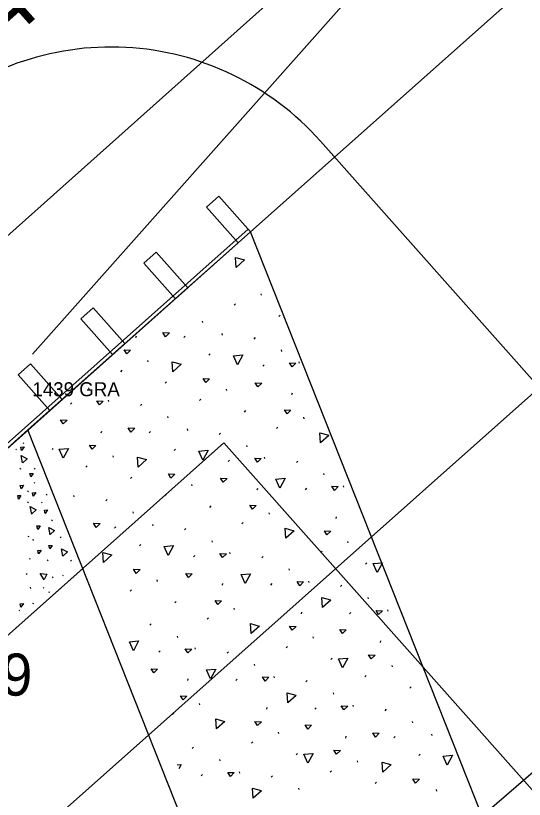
# Model space of a CAD drawing. Extents: x 49683 to 58852, y 49525 to 54803.
# Drawn here: x 55264.7 to 55301, y 53044.6 to 53100.5 of the extents above; entities that cross this region are included whole.
import ezdxf

# ---------------------------------------------------------------- set-up
doc = ezdxf.new("R2010")
doc.units = 0
for name, color, linetype in [('Level 11', 7, 'Continuous'), ('Level 13', 7, 'Continuous'), ('Level 15', 7, 'Continuous'), ('Level 18', 7, 'Continuous'), ('Level 19', 7, 'Continuous'), ('Level 20', 7, 'Continuous'), ('Level 27', 7, 'Continuous'), ('Level 3', 7, 'Continuous'), ('Level 32', 7, 'Continuous'), ('Level 48', 7, 'Continuous'), ('Level 57', 7, 'Continuous'), ('Level 7', 7, 'Continuous'), ('Level 8', 7, 'Continuous')]:
    doc.layers.add(name, color=color, linetype=linetype)

msp = doc.modelspace()

# ---------------------------------------------------------------- linework, layer by layer
at = {"layer": 'Level 11'}
msp.add_line((55223.521, 52979.087), (55416.975, 53146.156), dxfattribs=at)
at = {"layer": 'Level 13'}
for p, q in [((55279.532, 53069.998), (53969.027, 51905.114)), ((55307.435, 53038.607), (55279.532, 53069.998))]:
    msp.add_line(p, q, dxfattribs=at)
at = {"layer": 'Level 15'}
for p, q in [((55281.433, 53085.069), (55371.123, 53164.793)), ((55265.526, 53070.929), (55281.433, 53085.069)), ((55298.696, 53041.543), (55281.433, 53085.069)), ((55282.23, 53080.542), (55282.206, 53080.639)), ((55280.357, 53079.939), (55280.262, 53079.84)), ((55283.556, 53079.114), (55283.461, 53079.016)), ((55278.031, 53078.592), (55278.008, 53078.689)), ((55273.252, 53077.518), (55273.281, 53077.641)), ((55279.432, 53077.706), (55279.408, 53077.803)), ((55276.776, 53077.625), (55276.681, 53077.526)), ((55281.778, 53077.517), (55281.683, 53077.418)), ((55283.669, 53076.539), (55283.646, 53076.637)), ((55278.563, 53076.369), (55278.469, 53076.27)), ((55274.114, 53075.788), (55274.091, 53075.885)), ((55282.414, 53075.572), (55282.319, 53075.474)), ((55284.936, 53075.703), (55284.912, 53075.8)), ((55272.241, 53075.185), (55272.146, 53075.087)), ((55275.44, 53074.36), (55275.346, 53074.262)), ((55269.916, 53073.838), (55269.892, 53073.935)), ((55279.752, 53073.736), (55279.729, 53073.833)), ((55284.394, 53073.463), (55284.423, 53073.585)), ((55268.661, 53072.871), (55268.566, 53072.772)), ((55271.317, 53072.952), (55271.293, 53073.049)), ((55273.663, 53072.763), (55273.568, 53072.665)), ((55277.879, 53073.133), (55277.784, 53073.035)), ((55281.079, 53072.308), (55280.984, 53072.21)), ((55275.554, 53071.786), (55275.53, 53071.883)), ((55285.256, 53071.733), (55285.233, 53071.83)), ((55253.595, 53060.324), (55265.526, 53070.929)), ((55282.788, 53027.404), (55265.526, 53070.929)), ((55276.955, 53070.9), (55276.931, 53070.997)), ((55283.383, 53071.13), (55283.288, 53071.031)), ((55270.774, 53070.713), (55270.804, 53070.835)), ((55274.299, 53070.819), (55274.204, 53070.72)), ((55279.301, 53070.711), (55279.206, 53070.613)), ((55281.192, 53069.734), (55281.169, 53069.831)), ((55267.325, 53069.607), (55267.262, 53069.541)), ((55276.086, 53069.563), (55275.991, 53069.464)), ((55271.637, 53068.982), (55271.613, 53069.079)), ((55279.937, 53068.767), (55279.842, 53068.668)), ((55282.459, 53068.897), (55282.435, 53068.994)), ((55284.805, 53068.708), (55284.71, 53068.609)), ((55269.764, 53068.379), (55269.669, 53068.281)), ((55286.696, 53067.73), (55286.673, 53067.828)), ((55272.963, 53067.554), (55272.868, 53067.456)), ((55277.275, 53066.93), (55277.252, 53067.027)), ((55281.916, 53066.657), (55281.946, 53066.779)), ((55285.441, 53066.763), (55285.346, 53066.665)), ((55288.097, 53066.845), (55288.073, 53066.942)), ((55268.839, 53066.146), (55268.816, 53066.244)), ((55271.186, 53065.957), (55271.091, 53065.859)), ((55275.402, 53066.327), (55275.307, 53066.229)), ((55278.602, 53065.502), (55278.507, 53065.404)), ((55273.077, 53064.98), (55273.053, 53065.077)), ((55282.779, 53064.927), (55282.756, 53065.024)), ((55280.906, 53064.324), (55280.811, 53064.226)), ((55287.555, 53064.605), (55287.584, 53064.727)), ((55271.822, 53064.013), (55271.727, 53063.914)), ((55274.478, 53064.094), (55274.454, 53064.192)), ((55276.824, 53063.905), (55276.729, 53063.807)), ((55273.609, 53062.757), (55273.514, 53062.659)), ((55278.715, 53062.928), (55278.692, 53063.025)), ((55288.417, 53062.875), (55288.394, 53062.972)), ((55279.982, 53062.091), (55279.958, 53062.188)), ((55286.544, 53062.272), (55286.449, 53062.173)), ((55277.46, 53061.961), (55277.365, 53061.862)), ((55282.328, 53061.902), (55282.233, 53061.804)), ((55289.744, 53061.447), (55289.649, 53061.349)), ((55245.587, 53039.827), (55269.449, 53061.037)), ((55284.219, 53060.925), (55284.195, 53061.022)), ((55274.798, 53060.124), (55274.775, 53060.221)), ((55279.439, 53059.851), (55279.469, 53059.974)), ((55282.964, 53059.958), (55282.869, 53059.859)), ((55285.62, 53060.039), (55285.596, 53060.136)), ((55287.966, 53059.85), (55287.871, 53059.751)), ((55272.925, 53059.521), (55272.83, 53059.423)), ((55276.124, 53058.696), (55276.029, 53058.598)), ((55289.857, 53058.872), (55289.834, 53058.97)), ((55280.302, 53058.121), (55280.278, 53058.218)), ((55291.258, 53057.987), (55291.234, 53058.084)), ((55278.429, 53057.518), (55278.334, 53057.42)), ((55285.077, 53057.799), (55285.107, 53057.921)), ((55288.602, 53057.905), (55288.507, 53057.807)), ((55274.347, 53057.099), (55274.252, 53057.001)), ((55276.238, 53056.122), (55276.214, 53056.219)), ((55285.94, 53056.069), (55285.917, 53056.166)), ((55290.716, 53055.747), (55290.745, 53055.869)), ((55277.504, 53055.285), (55277.481, 53055.382)), ((55284.067, 53055.466), (55283.972, 53055.368)), ((55274.983, 53055.155), (55274.888, 53055.057)), ((55279.851, 53055.096), (55279.756, 53054.998)), ((55281.742, 53054.119), (55281.718, 53054.216)), ((55287.266, 53054.641), (55287.171, 53054.543)), ((55291.578, 53054.017), (55291.555, 53054.114)), ((55276.962, 53053.046), (55276.992, 53053.168)), ((55280.487, 53053.152), (55280.392, 53053.053)), ((55283.143, 53053.233), (55283.119, 53053.33)), ((55285.489, 53053.044), (55285.394, 53052.946)), ((55289.705, 53053.414), (55289.61, 53053.315)), ((55292.905, 53052.589), (55292.81, 53052.491)), ((55287.38, 53052.067), (55287.356, 53052.164)), ((55277.825, 53051.315), (55277.801, 53051.412)), ((55282.6, 53050.993), (55282.63, 53051.116)), ((55286.125, 53051.1), (55286.03, 53051.001)), ((55288.781, 53051.181), (55288.757, 53051.278)), ((55291.127, 53050.992), (55291.032, 53050.893)), ((55275.952, 53050.712), (55275.857, 53050.614)), ((55293.018, 53050.014), (55292.995, 53050.112)), ((55283.463, 53049.263), (55283.439, 53049.36)), ((55294.419, 53049.129), (55294.395, 53049.226)), ((55281.59, 53048.66), (55281.495, 53048.562)), ((55288.239, 53048.941), (55288.268, 53049.063)), ((55291.763, 53049.047), (55291.668, 53048.949)), ((55277.374, 53048.29), (55277.279, 53048.192)), ((55284.789, 53047.835), (55284.694, 53047.737)), ((55293.55, 53047.792), (55293.456, 53047.693)), ((55279.265, 53047.313), (55279.241, 53047.41)), ((55289.101, 53047.211), (55289.078, 53047.308)), ((55278.01, 53046.346), (55277.915, 53046.247)), ((55280.665, 53046.427), (55280.642, 53046.524)), ((55287.228, 53046.608), (55287.133, 53046.51)), ((55283.012, 53046.238), (55282.917, 53046.14)), ((55290.427, 53045.783), (55290.333, 53045.685)), ((55284.903, 53045.261), (55284.879, 53045.358)), ((55294.739, 53045.159), (55294.716, 53045.256))]:
    msp.add_line(p, q, dxfattribs=at)
for points in [[(55281.007, 53083.062), (55280.413, 53082.525), (55280.363, 53083.237), (55280.994, 53083.066)], [(55275.644, 53077.856), (55275.369, 53077.587), (55275.179, 53077.877), (55275.644, 53077.856)], [(55272.869, 53076.625), (55272.594, 53076.356), (55272.404, 53076.647), (55272.869, 53076.625)], [(55280.877, 53076.285), (55280.503, 53075.577), (55280.211, 53076.229), (55280.863, 53076.285)], [(55276.485, 53075.617), (55275.891, 53075.081), (55275.84, 53075.793), (55276.472, 53075.622)], [(55284.674, 53075.695), (55284.399, 53075.426), (55284.209, 53075.717), (55284.674, 53075.695)], [(55278.507, 53074.573), (55278.232, 53074.304), (55278.042, 53074.595), (55278.507, 53074.573)], [(55282.234, 53074.272), (55281.959, 53074.003), (55281.769, 53074.294), (55282.234, 53074.272)], [(55270.92, 53072.994), (55270.645, 53072.725), (55270.456, 53073.015), (55270.92, 53072.994)], [(55284.322, 53072.344), (55284.047, 53072.075), (55283.858, 53072.365), (55284.322, 53072.344)], [(55268.331, 53071.625), (55268.056, 53071.356), (55267.867, 53071.646), (55268.331, 53071.625)], [(55273.167, 53071.05), (55272.892, 53070.781), (55272.702, 53071.071), (55273.167, 53071.05)], [(55287.03, 53070.541), (55286.436, 53070.004), (55286.385, 53070.716), (55287.017, 53070.545)], [(55270.392, 53069.819), (55270.117, 53069.55), (55269.927, 53069.841), (55270.392, 53069.819)], [(55268.436, 53069.615), (55268.061, 53068.907), (55267.77, 53069.56), (55268.422, 53069.615)], [(55278.4, 53069.479), (55278.025, 53068.771), (55277.734, 53069.423), (55278.386, 53069.479)], [(55274.008, 53068.811), (55273.414, 53068.275), (55273.363, 53068.987), (55273.995, 53068.816)], [(55282.197, 53068.889), (55281.922, 53068.62), (55281.732, 53068.911), (55282.197, 53068.889)], [(55276.03, 53067.767), (55275.755, 53067.498), (55275.565, 53067.789), (55276.03, 53067.767)], [(55279.756, 53067.466), (55279.481, 53067.197), (55279.292, 53067.488), (55279.756, 53067.466)], [(55283.904, 53067.476), (55283.529, 53066.768), (55283.238, 53067.42), (55283.89, 53067.476)], [(55287.701, 53066.886), (55287.426, 53066.617), (55287.236, 53066.907), (55287.701, 53066.886)], [(55281.845, 53065.538), (55281.57, 53065.269), (55281.38, 53065.559), (55281.845, 53065.538)], [(55270.69, 53064.244), (55270.415, 53063.975), (55270.225, 53064.266), (55270.69, 53064.244)], [(55284.553, 53063.735), (55283.959, 53063.198), (55283.908, 53063.91), (55284.54, 53063.739)], [(55287.172, 53063.712), (55286.897, 53063.443), (55286.707, 53063.733), (55287.172, 53063.712)], [(55275.923, 53062.673), (55275.548, 53061.965), (55275.257, 53062.618), (55275.909, 53062.673)], [(55271.531, 53062.006), (55270.937, 53061.469), (55270.886, 53062.181), (55271.518, 53062.01)], [(55279.72, 53062.083), (55279.445, 53061.814), (55279.255, 53062.105), (55279.72, 53062.083)], [(55290.854, 53061.455), (55290.479, 53060.748), (55290.188, 53061.4), (55290.84, 53061.455)], [(55273.553, 53060.961), (55273.278, 53060.692), (55273.088, 53060.983), (55273.553, 53060.961)], [(55277.279, 53060.661), (55277.004, 53060.391), (55276.815, 53060.682), (55277.279, 53060.661)], [(55281.427, 53060.67), (55281.052, 53059.962), (55280.761, 53060.614), (55281.413, 53060.67)], [(55285.224, 53060.08), (55284.948, 53059.811), (55284.759, 53060.102), (55285.224, 53060.08)], [(55279.368, 53058.732), (55279.093, 53058.463), (55278.903, 53058.754), (55279.368, 53058.732)], [(55287.17, 53058.791), (55286.576, 53058.254), (55286.525, 53058.966), (55287.157, 53058.795)], [(55290.862, 53058.028), (55290.587, 53057.759), (55290.397, 53058.05), (55290.862, 53058.028)], [(55282.076, 53056.929), (55281.482, 53056.392), (55281.431, 53057.105), (55282.063, 53056.934)], [(55284.695, 53056.906), (55284.42, 53056.637), (55284.23, 53056.927), (55284.695, 53056.906)], [(55288.272, 53056.659), (55287.997, 53056.39), (55287.808, 53056.681), (55288.272, 53056.659)], [(55273.446, 53055.867), (55273.071, 53055.16), (55272.78, 53055.812), (55273.432, 53055.867)], [(55277.242, 53055.278), (55276.967, 53055.009), (55276.778, 53055.299), (55277.242, 53055.278)], [(55290.333, 53054.854), (55290.058, 53054.585), (55289.868, 53054.875), (55290.333, 53054.854)], [(55288.377, 53054.65), (55288.002, 53053.942), (55287.711, 53054.594), (55288.363, 53054.649)], [(55274.802, 53053.855), (55274.527, 53053.586), (55274.338, 53053.876), (55274.802, 53053.855)], [(55278.95, 53053.864), (55278.575, 53053.156), (55278.284, 53053.809), (55278.936, 53053.864)], [(55282.746, 53053.274), (55282.471, 53053.005), (55282.282, 53053.296), (55282.746, 53053.274)], [(55276.891, 53051.926), (55276.616, 53051.657), (55276.426, 53051.948), (55276.891, 53051.926)], [(55284.693, 53051.985), (55284.099, 53051.448), (55284.048, 53052.16), (55284.68, 53051.989)], [(55288.385, 53051.222), (55288.109, 53050.953), (55287.92, 53051.244), (55288.385, 53051.222)], [(55279.599, 53050.123), (55279.005, 53049.586), (55278.954, 53050.299), (55279.586, 53050.128)], [(55282.217, 53050.1), (55281.943, 53049.831), (55281.753, 53050.122), (55282.217, 53050.1)], [(55285.795, 53049.853), (55285.52, 53049.584), (55285.331, 53049.875), (55285.795, 53049.853)], [(55290.631, 53049.279), (55290.356, 53049.01), (55290.166, 53049.3), (55290.631, 53049.279)], [(55287.856, 53048.048), (55287.581, 53047.779), (55287.391, 53048.069), (55287.856, 53048.048)], [(55285.9, 53047.844), (55285.525, 53047.136), (55285.234, 53047.788), (55285.886, 53047.844)], [(55295.864, 53047.708), (55295.49, 53047), (55295.198, 53047.652), (55295.85, 53047.708)], [(55276.188, 53047.035), (55276.459, 53047.058)], [(55276.473, 53047.058), (55276.305, 53046.741)], [(55291.472, 53047.04), (55290.878, 53046.503), (55290.827, 53047.216), (55291.459, 53047.045)], [(55280.269, 53046.468), (55279.994, 53046.199), (55279.805, 53046.49), (55280.269, 53046.468)], [(55293.494, 53045.996), (55293.219, 53045.727), (55293.029, 53046.017), (55293.494, 53045.996)], [(55282.216, 53045.179), (55281.622, 53044.642), (55281.571, 53045.355), (55282.203, 53045.184)]]:
    msp.add_lwpolyline(points, dxfattribs=at)
at = {"layer": 'Level 18'}
msp.add_line((55315.468, 53058.871), (55286.422, 53091.547), dxfattribs=at)
msp.add_arc((55271.474, 53078.26), 20, 41.6334, 132.3101, dxfattribs=at)
at = {"layer": 'Level 19'}
msp.add_line((54181.768, 52078.16), (56150.851, 53828.445), dxfattribs=at)
at = {"layer": 'Level 20'}
msp.add_line((54173.795, 52087.129), (55269.449, 53061.037), dxfattribs=at)
at = {"layer": 'Level 27'}
for p, q in [((55278.291, 53086.826), (55279.175, 53087.611)), ((55279.175, 53087.611), (55281.433, 53085.069)), ((55280.55, 53084.284), (55278.291, 53086.826)), ((55239.225, 53047.886), (55281.267, 53085.256)), ((55239.391, 53047.699), (55281.433, 53085.069)), ((55281.433, 53085.069), (55280.55, 53084.284)), ((55273.806, 53082.84), (55274.69, 53083.625)), ((55274.69, 53083.625), (55276.948, 53081.084)), ((55276.065, 53080.298), (55273.806, 53082.84)), ((55276.948, 53081.084), (55276.065, 53080.298)), ((55269.321, 53078.854), (55270.205, 53079.64)), ((55270.205, 53079.64), (55272.463, 53077.098)), ((55271.58, 53076.313), (55269.321, 53078.854)), ((55272.463, 53077.098), (55271.58, 53076.313)), ((55264.836, 53074.869), (55265.72, 53075.654)), ((55265.72, 53075.654), (55267.978, 53073.113)), ((55267.094, 53072.327), (55264.836, 53074.869)), ((55267.978, 53073.113), (55267.094, 53072.327))]:
    msp.add_line(p, q, dxfattribs=at)
at = {"layer": 'Level 3'}
msp.add_line((55241.707, 53064.82), (55317.341, 53132.327), dxfattribs=at)
at = {"layer": 'Level 7'}
msp.add_line((55265.855, 53076.335), (55290.983, 53104.582), dxfattribs=at)
at = {"layer": 'Level 8'}
for p, q in [((55265.189, 53070.013), (55265.248, 53069.954)), ((55264.663, 53069.567), (55264.722, 53069.508)), ((55264.966, 53068.191), (55265.026, 53068.132)), ((55265.977, 53068.191), (55266.037, 53068.132)), ((55265.977, 53067.179), (55266.037, 53067.12)), ((55265.512, 53066.592), (55265.572, 53066.533)), ((55266.847, 53066.349), (55266.906, 53066.29)), ((55265.512, 53065.802), (55265.572, 53065.743)), ((55266.503, 53065.782), (55266.563, 53065.723)), ((55267.231, 53064.507), (55267.291, 53064.448)), ((55265.541, 53063.354), (55265.605, 53063.334)), ((55265.935, 53063.036), (55265.912, 53063.124)), ((55267.838, 53063.293), (55267.897, 53063.234)), ((55265.629, 53061.761), (55265.693, 53061.74)), ((55266.914, 53061.652), (55266.973, 53061.593)), ((55268.566, 53061.633), (55268.626, 53061.574)), ((55265.411, 53060.682), (55265.47, 53060.623)), ((55267.272, 53060.439), (55267.331, 53060.38)), ((55268.002, 53060.568), (55268.065, 53060.547)), ((55265.753, 53059.608), (55265.73, 53059.696)), ((55266.625, 53059.69), (55266.684, 53059.631)), ((55267.081, 53059.297), (55267.058, 53059.385)), ((55264.879, 53058.067), (55264.943, 53058.047)), ((55265.869, 53058.558), (55265.932, 53058.538)), ((55265.311, 53057.739), (55265.311, 53057.739)), ((55265.442, 53057.843), (55265.442, 53057.843))]:
    msp.add_line(p, q, dxfattribs=at)
for points in [[(55265.088, 53069.457), (55265.03, 53069.707), (55265.262, 53069.714), (55265.088, 53069.457)], [(55265.157, 53068.573), (55265.057, 53069.097), (55265.48, 53068.879), (55265.164, 53068.579)], [(55265.736, 53067.575), (55265.678, 53067.824), (55265.909, 53067.832), (55265.736, 53067.575)], [(55265.048, 53066.724), (55264.99, 53066.974), (55265.221, 53066.982), (55265.048, 53066.724)], [(55265.918, 53066.198), (55265.86, 53066.448), (55266.091, 53066.455), (55265.918, 53066.198)], [(55264.866, 53065.996), (55264.808, 53066.246), (55265.039, 53066.253), (55264.866, 53065.996)], [(55265.804, 53064.93), (55265.704, 53065.454), (55266.128, 53065.236), (55265.811, 53064.935)], [(55266.767, 53064.964), (55266.709, 53065.213), (55266.94, 53065.221), (55266.767, 53064.964)], [(55266.241, 53063.83), (55266.183, 53064.08), (55266.415, 53064.087), (55266.241, 53063.83)], [(55267.119, 53063.452), (55267.019, 53063.976), (55267.442, 53063.758), (55267.126, 53063.458)], [(55267.091, 53062.433), (55267.033, 53062.683), (55267.264, 53062.691), (55267.091, 53062.433)], [(55266.301, 53062.081), (55266.243, 53062.331), (55266.474, 53062.338), (55266.301, 53062.081)], [(55268.029, 53061.914), (55267.929, 53062.438), (55268.352, 53062.22), (55268.036, 53061.92)], [(55266.691, 53060.237), (55266.418, 53060.695), (55266.89, 53060.635), (55266.696, 53060.245)], [(55265.04, 53058.279), (55264.982, 53058.528), (55265.213, 53058.536), (55265.04, 53058.279)]]:
    msp.add_lwpolyline(points, dxfattribs=at)

# ---------------------------------------------------------------- texts
at = {"layer": 'Level 32'}
msp.add_text('267.39', height=3, dxfattribs=at).set_placement((55253.584, 53051.967))
at = {"layer": 'Level 48'}
msp.add_text("44'C", height=5, rotation=41.6334, dxfattribs=at).set_placement((55261.115, 53095.875))
at = {"layer": 'Level 57'}
msp.add_text('1439 GRA', height=1, dxfattribs=at).set_placement((55265.855, 53073.335))

doc.saveas('drawing.dxf')
